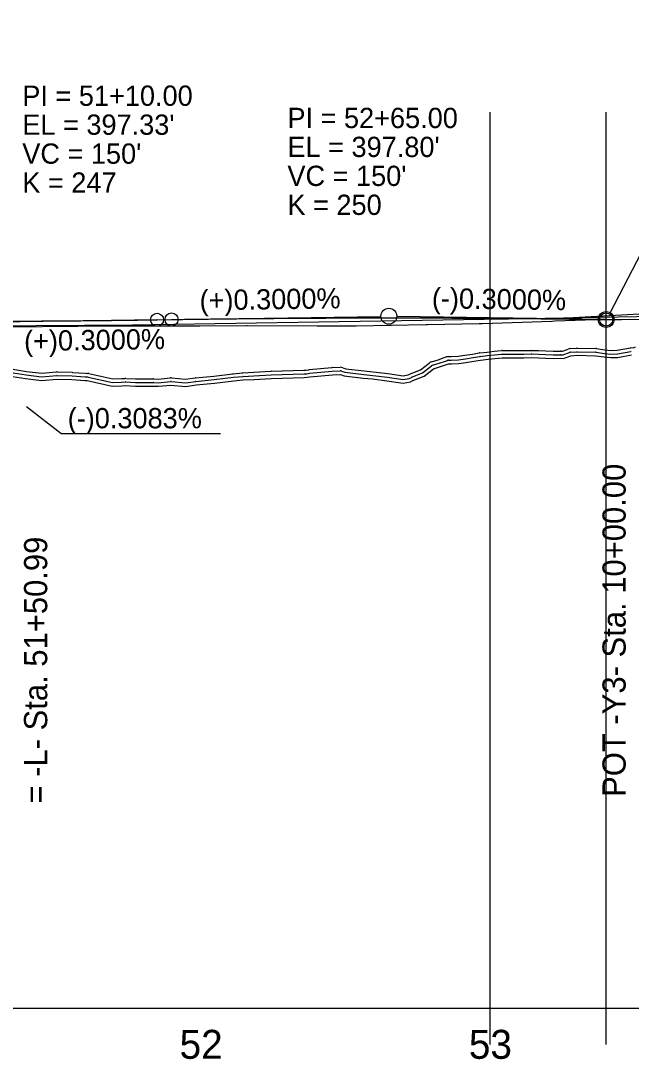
# Model space of a CAD drawing. Extents: x 1625686 to 1640492, y 1161393 to 1175642.
# Drawn here: x 1634342.3 to 1634553, y 1174893.1 to 1175251.8 of the extents above; entities that cross this region are included whole.
import ezdxf

# ---------------------------------------------------------------- set-up
doc = ezdxf.new("R2010")
doc.units = 0
for name, color, linetype in [('Exist Profile Cell', 7, 'Continuous'), ('Exist Vertical Profile Ground Line', 7, 'Continuous'), ('Exist Vertical Profile Horizontal Axis Label Major', 7, 'Continuous'), ('Prop PFL Text', 7, 'Continuous'), ('Prop Vertical Profile Curve Label', 7, 'Continuous'), ('Prop Vertical Profile Grade', 7, 'Continuous'), ('Prop Vertical Profile Grade Label', 7, 'Continuous'), ('Prop VPI Label', 7, 'Continuous'), ('Scratch_Level_1', 7, 'Continuous'), ('Scratch_Level_3', 7, 'Continuous'), ('Scratch_Level_5', 7, 'Continuous'), ('Scratch_Level_7', 7, 'Continuous')]:
    doc.layers.add(name, color=color, linetype=linetype)

msp = doc.modelspace()

# ---------------------------------------------------------------- linework, layer by layer
at = {"layer": 'Exist Profile Cell'}
msp.add_line((1630204.31, 1174910.79), (1634670.63, 1174910.79), dxfattribs=at)
at = {"layer": 'Exist Vertical Profile Ground Line'}
msp.add_lwpolyline([(1634337.45, 1175146.14), (1634362, 1175146.32), (1634378.19, 1175146.44), (1634379.03, 1175146.45), (1634403.14, 1175146.49), (1634404.05, 1175146.49), (1634420.01, 1175146.52), (1634420.37, 1175146.52), (1634444.57, 1175146.49), (1634445.37, 1175146.49), (1634457.31, 1175146.48), (1634458, 1175146.48), (1634482.19, 1175146.89), (1634482.67, 1175146.91), (1634500.47, 1175147.21), (1634501.6, 1175147.25), (1634525.53, 1175148.12), (1634526.58, 1175148.15), (1634540.63, 1175148.66), (1634541.63, 1175148.67), (1634544.03, 1175148.63), (1634549.61, 1175148.68), (1634561.05, 1175148.7)], dxfattribs=at)
at = {"layer": 'Prop Vertical Profile Curve Label'}
for centre in [(1634389.31, 1175148.56), (1634394.31, 1175148.64), (1634544.31, 1175148.64), (1634544.31, 1175148.64)]:
    msp.add_circle(centre, 2.25, dxfattribs=at)
at = {"layer": 'Prop Vertical Profile Grade'}
msp.add_line((1634389.31, 1175148.56), (1634394.31, 1175148.64), dxfattribs=at)
for points in [[(1634239.31, 1175148.59), (1634242.31, 1175148.55), (1634245.31, 1175148.5), (1634248.31, 1175148.46), (1634251.31, 1175148.42), (1634254.31, 1175148.38), (1634257.31, 1175148.35), (1634260.31, 1175148.31), (1634263.31, 1175148.28), (1634266.31, 1175148.25), (1634269.31, 1175148.22), (1634272.31, 1175148.19), (1634275.31, 1175148.17), (1634278.31, 1175148.15), (1634281.31, 1175148.12), (1634284.31, 1175148.1), (1634287.31, 1175148.09), (1634290.31, 1175148.07), (1634293.31, 1175148.06), (1634296.31, 1175148.04), (1634299.31, 1175148.03), (1634302.31, 1175148.02), (1634305.31, 1175148.02), (1634308.31, 1175148.01), (1634311.31, 1175148.01), (1634314.31, 1175148.01), (1634317.31, 1175148.01), (1634320.31, 1175148.01), (1634323.31, 1175148.01), (1634326.31, 1175148.02), (1634329.31, 1175148.03), (1634332.31, 1175148.04), (1634335.31, 1175148.05), (1634338.31, 1175148.06), (1634341.31, 1175148.08), (1634344.31, 1175148.09), (1634347.31, 1175148.11), (1634350.31, 1175148.13), (1634353.31, 1175148.15), (1634356.31, 1175148.18), (1634359.31, 1175148.2), (1634362.31, 1175148.23), (1634365.31, 1175148.26), (1634368.31, 1175148.29), (1634371.31, 1175148.32), (1634374.31, 1175148.36), (1634377.31, 1175148.4), (1634380.31, 1175148.43), (1634383.31, 1175148.48), (1634386.31, 1175148.52), (1634389.31, 1175148.56)], [(1634394.31, 1175148.64), (1634397.31, 1175148.68), (1634400.31, 1175148.72), (1634403.31, 1175148.76), (1634406.31, 1175148.8), (1634409.31, 1175148.84), (1634412.31, 1175148.87), (1634415.31, 1175148.91), (1634418.31, 1175148.94), (1634421.31, 1175148.97), (1634424.31, 1175149), (1634427.31, 1175149.02), (1634430.31, 1175149.05), (1634433.31, 1175149.07), (1634436.31, 1175149.09), (1634439.31, 1175149.11), (1634442.31, 1175149.13), (1634445.31, 1175149.14), (1634448.31, 1175149.16), (1634451.31, 1175149.17), (1634454.31, 1175149.18), (1634457.31, 1175149.18), (1634460.31, 1175149.19), (1634463.31, 1175149.2), (1634466.31, 1175149.2), (1634469.31, 1175149.2), (1634472.31, 1175149.2), (1634475.31, 1175149.2), (1634478.31, 1175149.19), (1634481.31, 1175149.18), (1634484.31, 1175149.18), (1634487.31, 1175149.17), (1634490.31, 1175149.16), (1634493.31, 1175149.14), (1634496.31, 1175149.13), (1634499.31, 1175149.11), (1634502.31, 1175149.09), (1634505.31, 1175149.07), (1634508.31, 1175149.05), (1634511.31, 1175149.02), (1634514.31, 1175149), (1634517.31, 1175148.97), (1634520.31, 1175148.94), (1634523.31, 1175148.91), (1634526.31, 1175148.87), (1634529.31, 1175148.84), (1634532.31, 1175148.8), (1634535.31, 1175148.76), (1634538.31, 1175148.72), (1634541.31, 1175148.68), (1634544.31, 1175148.64)]]:
    msp.add_spline(points, degree=3, dxfattribs=at)
at = {"layer": 'Prop VPI Label'}
for p, q in [((1634545.73, 1175151), (1634597.75, 1175251.82)), ((1634389.31, 1175148.56), (1634317.06, 1175147.48)), ((1634394.31, 1175148.64), (1634466.56, 1175149.72)), ((1634544.31, 1175148.64), (1634472.06, 1175149.72)), ((1634356.12, 1175109.32), (1634344.22, 1175118.52)), ((1634356.12, 1175109.32), (1634411.25, 1175109.32))]:
    msp.add_line(p, q, dxfattribs=at)
for centre in [(1634469.31, 1175149.76), (1634544.31, 1175148.64), (1634544.31, 1175148.64)]:
    msp.add_circle(centre, 2.75, dxfattribs=at)
at = {"layer": 'Scratch_Level_1'}
for p, q in [((1634505.67, 1175137.69), (1634508.17, 1175137.93)), ((1634508.43, 1175137.94), (1634510.93, 1175137.93)), ((1634518.55, 1175137.99), (1634521.07, 1175137.9)), ((1634531.87, 1175138.58), (1634534.07, 1175138.76)), ((1634531.97, 1175137.34), (1634534.17, 1175137.52)), ((1634534.31, 1175137.52), (1634540.68, 1175137.36)), ((1634534.34, 1175138.77), (1634540.72, 1175138.61)), ((1634488.42, 1175135.46), (1634489.12, 1175135.7)), ((1634488.82, 1175134.28), (1634489.53, 1175134.52)), ((1634498.18, 1175136.72), (1634500.52, 1175137.09)), ((1634498.38, 1175135.48), (1634500.72, 1175135.86)), ((1634505.79, 1175136.45), (1634508.29, 1175136.69)), ((1634508.42, 1175136.69), (1634510.92, 1175136.68)), ((1634518.5, 1175136.74), (1634521.03, 1175136.65)), ((1634354.88, 1175130.52), (1634360.01, 1175130.4)), ((1634415.56, 1175129.93), (1634418.83, 1175130.25)), ((1634441.85, 1175131.33), (1634449.58, 1175132.05)), ((1634441.97, 1175130.09), (1634449.69, 1175130.8)), ((1634449.73, 1175132.06), (1634452.51, 1175132.14)), ((1634449.77, 1175130.81), (1634452.55, 1175130.89)), ((1634463.95, 1175130.59), (1634468.94, 1175129.98)), ((1634476.66, 1175129.84), (1634477.55, 1175130.22)), ((1634354.85, 1175129.27), (1634359.98, 1175129.15)), ((1634415.68, 1175128.69), (1634418.95, 1175129)), ((1634463.8, 1175129.35), (1634468.79, 1175128.74)), ((1634477.14, 1175128.69), (1634478.04, 1175129.07))]:
    msp.add_line(p, q, dxfattribs=at)
for points in [[(1634500.63, 1175137.11), (1634503.24, 1175137.4), (1634505.62, 1175137.68)], [(1634510.93, 1175137.93), (1634513.42, 1175137.91), (1634514.47, 1175137.91), (1634515.88, 1175137.91), (1634518.38, 1175137.99)], [(1634521.11, 1175137.9), (1634523.51, 1175137.77), (1634526.05, 1175137.71), (1634528.56, 1175137.74)], [(1634528.75, 1175137.74), (1634529.26, 1175137.7), (1634531.19, 1175138.43)], [(1634540.83, 1175137.34), (1634543.74, 1175136.93), (1634545.95, 1175136.71), (1634548.22, 1175136.81), (1634552.87, 1175137.63)], [(1634541, 1175138.58), (1634543.89, 1175138.17), (1634545.98, 1175137.97), (1634548.08, 1175138.06), (1634552.65, 1175138.86)], [(1634552.82, 1175138.89), (1634553.83, 1175139), (1634553.92, 1175139.01), (1634554.44, 1175139.2)], [(1634484.02, 1175134.03), (1634486.34, 1175134.74), (1634488.41, 1175135.46)], [(1634484.39, 1175132.84), (1634486.73, 1175133.56), (1634488.82, 1175134.28)], [(1634489.83, 1175135.84), (1634490.78, 1175135.88), (1634493.19, 1175135.98), (1634495.55, 1175136.29), (1634498.18, 1175136.72)], [(1634489.88, 1175134.59), (1634490.84, 1175134.63), (1634493.3, 1175134.73), (1634495.73, 1175135.06), (1634498.38, 1175135.48)], [(1634500.77, 1175135.87), (1634503.39, 1175136.16), (1634505.77, 1175136.44)], [(1634510.92, 1175136.68), (1634513.42, 1175136.66), (1634514.47, 1175136.66), (1634515.9, 1175136.66), (1634518.42, 1175136.74)], [(1634521.05, 1175136.65), (1634523.46, 1175136.52), (1634526.04, 1175136.46), (1634528.58, 1175136.49)], [(1634528.67, 1175136.49), (1634529.44, 1175136.44), (1634529.67, 1175136.52), (1634531.63, 1175137.26)], [(1634338.11, 1175130.44), (1634344.12, 1175129.49), (1634349.49, 1175128.86), (1634354.72, 1175129.27)], [(1634338.31, 1175131.68), (1634344.29, 1175130.73), (1634349.52, 1175130.12), (1634354.62, 1175130.51)], [(1634360.13, 1175130.39), (1634364.56, 1175130.06), (1634365.3, 1175130.04)], [(1634418.95, 1175130.26), (1634422.71, 1175130.45), (1634428.61, 1175130.77)], [(1634428.67, 1175130.77), (1634440, 1175131.12), (1634440.81, 1175131.16), (1634441.68, 1175131.31)], [(1634453.02, 1175130.82), (1634454.15, 1175130.41), (1634460.63, 1175129.66), (1634463.77, 1175129.35)], [(1634453.44, 1175131.99), (1634454.44, 1175131.63), (1634460.76, 1175130.9), (1634463.89, 1175130.6)], [(1634477.6, 1175130.24), (1634480.27, 1175131.3), (1634483.21, 1175133.61)], [(1634478.06, 1175129.08), (1634480.9, 1175130.2), (1634483.98, 1175132.63)], [(1634360.04, 1175129.14), (1634364.49, 1175128.81), (1634365.26, 1175128.79)], [(1634365.51, 1175128.76), (1634373.9, 1175126.85), (1634377.09, 1175127.01), (1634378.27, 1175127.07)], [(1634365.78, 1175129.98), (1634374.01, 1175128.11), (1634377.03, 1175128.26), (1634378.21, 1175128.32)], [(1634378.41, 1175127.07), (1634381.89, 1175126.85), (1634388.07, 1175126.92)], [(1634378.49, 1175128.32), (1634381.92, 1175128.1), (1634388.05, 1175128.17)], [(1634388.17, 1175126.92), (1634389.74, 1175126.81), (1634394.01, 1175127.2)], [(1634388.25, 1175128.17), (1634389.73, 1175128.07), (1634393.89, 1175128.45)], [(1634394.23, 1175127.2), (1634399.18, 1175126.76), (1634402.64, 1175127.27)], [(1634394.34, 1175128.45), (1634399.14, 1175128.02), (1634402.46, 1175128.5)], [(1634402.58, 1175128.52), (1634408.88, 1175129.12), (1634415.5, 1175129.92)], [(1634402.7, 1175127.28), (1634409.02, 1175127.88), (1634415.65, 1175128.68)], [(1634419.01, 1175129.01), (1634422.77, 1175129.2), (1634428.67, 1175129.52)], [(1634428.7, 1175129.53), (1634440.05, 1175129.88), (1634440.95, 1175129.92), (1634441.88, 1175130.07)], [(1634468.82, 1175128.74), (1634474.26, 1175127.94), (1634476.36, 1175128.31), (1634477.08, 1175128.66)], [(1634469, 1175129.97), (1634474.24, 1175129.21), (1634475.97, 1175129.51), (1634476.54, 1175129.79)]]:
    msp.add_lwpolyline(points, dxfattribs=at)
for centre, radius, start, end in [((1634505.91, 1175135.2), 2.5, 95.4963, 96.752), ((1634508.41, 1175135.44), 2.5, 89.6932, 95.4963), ((1634510.91, 1175135.43), 2.5, 89.6777, 89.6932), ((1634518.46, 1175135.49), 2.5, 87.9222, 91.8014), ((1634520.98, 1175135.4), 2.5, 87.0492, 87.9222), ((1634528.59, 1175135.24), 2.5, 86.342, 90.6303), ((1634532.07, 1175136.09), 2.5, 94.6742, 110.6376), ((1634532.07, 1175136.09), 1.25, 94.6742, 110.6376), ((1634534.28, 1175136.27), 2.5, 88.5173, 94.6742), ((1634534.28, 1175136.27), 1.25, 88.5173, 94.6742), ((1634540.65, 1175136.11), 1.25, 81.9622, 88.5173), ((1634540.65, 1175136.11), 2.5, 81.9622, 88.5173), ((1634553.08, 1175136.4), 2.5, 96.1835, 99.9774), ((1634553.08, 1175136.4), 1.25, 96.1835, 99.9774), ((1634484.75, 1175131.64), 2.5, 107.0188, 128.188), ((1634489.23, 1175133.1), 2.5, 108.9292, 109.0564), ((1634489.23, 1175133.1), 1.25, 108.9292, 109.0564), ((1634489.93, 1175133.34), 2.5, 92.4237, 108.9292), ((1634489.93, 1175133.34), 1.25, 92.4237, 108.9292), ((1634498.58, 1175134.25), 2.5, 99.1137, 99.1208), ((1634498.58, 1175134.25), 1.25, 99.1137, 99.1208), ((1634500.91, 1175134.62), 2.5, 96.433, 99.1137), ((1634500.91, 1175134.62), 1.25, 96.433, 99.1137), ((1634505.91, 1175135.2), 1.25, 95.4963, 96.752), ((1634508.41, 1175135.44), 1.25, 89.6932, 95.4963), ((1634510.91, 1175135.43), 1.25, 89.6777, 89.6932), ((1634518.46, 1175135.49), 1.25, 87.9222, 91.8014), ((1634520.98, 1175135.4), 1.25, 87.0492, 87.9222), ((1634528.59, 1175135.24), 1.25, 86.342, 90.6303), ((1634354.82, 1175128.02), 2.5, 88.6151, 94.4483), ((1634359.95, 1175127.9), 2.5, 85.7543, 88.6151), ((1634419.08, 1175127.76), 2.5, 92.9123, 95.5387), ((1634428.74, 1175128.28), 2.5, 91.7677, 93.1503), ((1634442.08, 1175128.84), 2.5, 95.2937, 99.3614), ((1634449.81, 1175129.56), 2.5, 91.8054, 95.2937), ((1634449.81, 1175129.56), 1.25, 91.8054, 95.2937), ((1634452.59, 1175129.64), 2.5, 70.0648, 91.8054), ((1634452.59, 1175129.64), 1.25, 70.0648, 91.8054), ((1634463.65, 1175128.11), 2.5, 83.034, 84.3731), ((1634478.52, 1175127.92), 2.5, 111.6055, 112.9332), ((1634484.75, 1175131.64), 1.25, 107.0188, 128.188), ((1634354.82, 1175128.02), 1.25, 88.6151, 94.4483), ((1634359.95, 1175127.9), 1.25, 85.7543, 88.6151), ((1634365.23, 1175127.54), 1.25, 77.1965, 88.4813), ((1634365.23, 1175127.54), 2.5, 77.1965, 88.4813), ((1634378.33, 1175125.82), 2.5, 86.347, 92.862), ((1634378.33, 1175125.82), 1.25, 86.347, 92.862), ((1634388.08, 1175125.67), 2.5, 86.1136, 90.6921), ((1634388.08, 1175125.67), 1.25, 86.1136, 90.6921), ((1634394.12, 1175125.96), 2.5, 84.9033, 95.1925), ((1634394.12, 1175125.96), 1.25, 84.9033, 95.1925), ((1634402.82, 1175126.03), 2.5, 95.4484, 98.3577), ((1634402.82, 1175126.03), 1.25, 95.4484, 98.3577), ((1634415.8, 1175127.44), 2.5, 95.5387, 96.9212), ((1634415.8, 1175127.44), 1.25, 95.5387, 96.9212), ((1634419.08, 1175127.76), 1.25, 92.9123, 95.5387), ((1634428.74, 1175128.28), 1.25, 91.7677, 93.1503), ((1634442.08, 1175128.84), 1.25, 95.2937, 99.3614), ((1634463.65, 1175128.11), 1.25, 83.034, 84.3731), ((1634468.64, 1175127.5), 1.25, 81.7193, 83.034), ((1634468.64, 1175127.5), 2.5, 81.7193, 83.034), ((1634477.63, 1175127.54), 2.5, 112.9332, 115.9662), ((1634477.63, 1175127.54), 1.25, 112.9332, 115.9662), ((1634478.52, 1175127.92), 1.25, 111.6055, 112.9332)]:
    msp.add_arc(centre, radius, start, end, dxfattribs=at)
at = {"layer": 'Scratch_Level_3'}
msp.add_lwpolyline([(1634330.81, 1175146.46), (1634380.81, 1175146.81), (1634430.81, 1175147.6), (1634480.81, 1175148.42), (1634530.81, 1175149.25), (1634580.81, 1175151.93)], dxfattribs=at)
at = {"layer": 'Scratch_Level_5'}
for p, q in [((1634504.31, 1174898.29), (1634504.31, 1175220.28)), ((1634544.31, 1174898.29), (1634544.31, 1175220.28))]:
    msp.add_line(p, q, dxfattribs=at)
msp.add_lwpolyline([(1634337.91, 1175129.21), (1634343.95, 1175128.25), (1634349.47, 1175127.6), (1634354.82, 1175128.02), (1634359.95, 1175127.9), (1634364.43, 1175127.56), (1634365.23, 1175127.54), (1634373.79, 1175125.6), (1634377.15, 1175125.76), (1634378.33, 1175125.82), (1634381.86, 1175125.6), (1634388.08, 1175125.67), (1634389.76, 1175125.56), (1634394.12, 1175125.96), (1634399.22, 1175125.5), (1634402.82, 1175126.03), (1634409.15, 1175126.64), (1634415.8, 1175127.44), (1634419.08, 1175127.76), (1634422.84, 1175127.95), (1634428.74, 1175128.28), (1634440.1, 1175128.63), (1634441.08, 1175128.68), (1634442.08, 1175128.84), (1634449.81, 1175129.56), (1634452.59, 1175129.64), (1634453.86, 1175129.18), (1634460.5, 1175128.42), (1634463.65, 1175128.11), (1634468.64, 1175127.5), (1634474.28, 1175126.68), (1634476.75, 1175127.11), (1634477.63, 1175127.54), (1634478.52, 1175127.92), (1634481.53, 1175129.11), (1634484.75, 1175131.64), (1634487.12, 1175132.37), (1634489.23, 1175133.1), (1634489.93, 1175133.34), (1634490.89, 1175133.38), (1634493.41, 1175133.49), (1634495.91, 1175133.82), (1634498.58, 1175134.25), (1634500.91, 1175134.62), (1634503.53, 1175134.92), (1634505.91, 1175135.2), (1634508.41, 1175135.44), (1634510.91, 1175135.43), (1634513.41, 1175135.41), (1634514.46, 1175135.41), (1634515.92, 1175135.41), (1634518.46, 1175135.49), (1634520.98, 1175135.4), (1634523.41, 1175135.27), (1634526.04, 1175135.21), (1634528.59, 1175135.24), (1634529.62, 1175135.18), (1634530.1, 1175135.35), (1634532.07, 1175136.09), (1634534.28, 1175136.27), (1634540.65, 1175136.11), (1634543.59, 1175135.69), (1634545.92, 1175135.46), (1634548.36, 1175135.57), (1634553.08, 1175136.4)], dxfattribs=at)
at = {"layer": 'Scratch_Level_7'}
msp.add_line((1634504.31, 1175148.81), (1634715.81, 1175152.31), dxfattribs=at)

# ---------------------------------------------------------------- texts
at = {"layer": 'Exist Vertical Profile Horizontal Axis Label Major'}
for s, p in [('52', (1634397.09, 1174893.29)), ('53', (1634496.92, 1174893.29))]:
    msp.add_text(s, height=10, dxfattribs=at).set_placement(p)
at = {"layer": 'Prop PFL Text'}
for s, p in [('POT -Y3- Sta. 10+00.00', (1634551.03, 1174983.76)), ('= -L- Sta. 51+50.99', (1634351.41, 1174981.45))]:
    msp.add_text(s, height=8, rotation=90, dxfattribs=at).set_placement(p)
at = {"layer": 'Prop Vertical Profile Curve Label'}
for s, p in [("VC = 150'", (1634342.81, 1175202.44)), ("VC = 150'", (1634434.31, 1175194.76)), ('K = 247', (1634342.81, 1175192.44)), ('K = 250', (1634434.31, 1175184.76))]:
    msp.add_text(s, height=7, dxfattribs=at).set_placement(p)
at = {"layer": 'Prop Vertical Profile Grade Label'}
for s, rotation, p in [('(+)0.3000%', 0.8594, (1634404.04, 1175151.78)), ('(-)0.3000%', 359.1406, (1634484.12, 1175152.54)), ('(+)0.3000%', 0.8594, (1634343.47, 1175137.71))]:
    msp.add_text(s, height=7, rotation=rotation, dxfattribs=at).set_placement(p)
msp.add_text('(-)0.3083%', height=7, dxfattribs=at).set_placement((1634358.47, 1175111.06))
at = {"layer": 'Prop VPI Label'}
for s, p in [('PI = 51+10.00', (1634342.81, 1175222.44)), ('PI = 52+65.00', (1634434.31, 1175214.76)), ("EL = 397.33'", (1634342.81, 1175212.44)), ("EL = 397.80'", (1634434.31, 1175204.76))]:
    msp.add_text(s, height=7, dxfattribs=at).set_placement(p)

doc.saveas('drawing.dxf')
